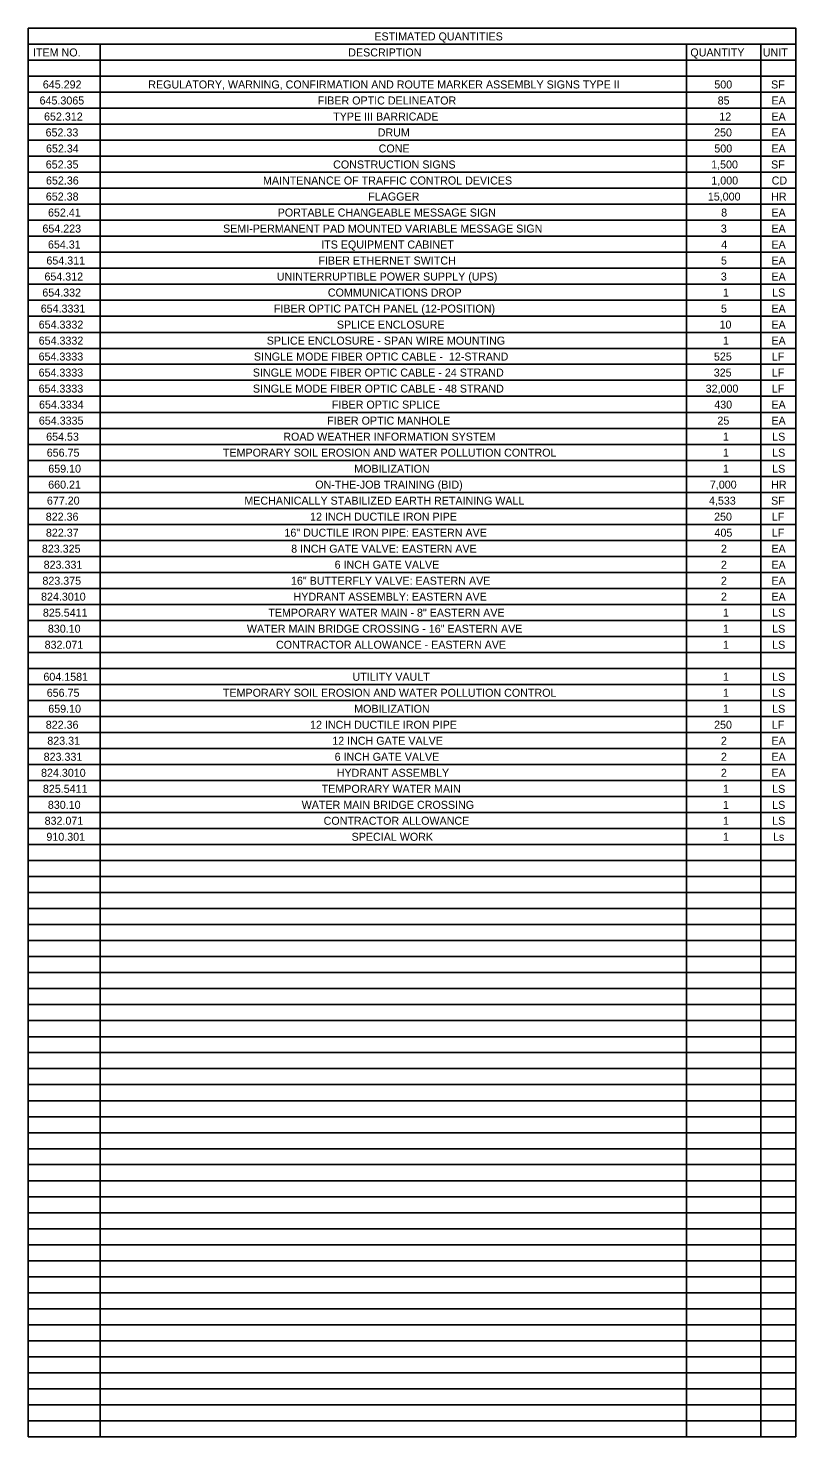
# Model space of a CAD drawing. Extents: x -18.7 to 5.6, y -2.7 to 4.
# Drawn here: x -5.186 to -4.242, y -0.822 to 0.91 of the extents above; entities that cross this region are included whole.
import ezdxf

# ---------------------------------------------------------------- set-up
doc = ezdxf.new("R2010")
doc.units = 0
doc.layers.add('ANNOTATION', color=7, linetype='Continuous')
doc.layers.add('BORDER', color=7, linetype='Continuous')

msp = doc.modelspace()

# ---------------------------------------------------------------- linework, layer by layer
at = {"layer": 'BORDER'}
for p, q in [((-5.186, 0.8907), (-4.2418, 0.8907)), ((-5.0975, 0.8907), (-5.0975, -0.822)), ((-4.3761, 0.8907), (-4.3761, -0.822)), ((-4.2848, 0.8907), (-4.2848, -0.822)), ((-5.186, 0.871), (-4.2418, 0.871)), ((-5.186, 0.8513), (-4.2418, 0.8513)), ((-5.186, 0.8316), (-4.2418, 0.8316)), ((-5.186, 0.8119), (-4.2418, 0.8119)), ((-5.186, 0.7922), (-4.2418, 0.7922)), ((-5.186, 0.7726), (-4.2418, 0.7726)), ((-5.186, 0.7529), (-4.2418, 0.7529)), ((-5.186, 0.7332), (-4.2418, 0.7332)), ((-5.186, 0.7135), (-4.2418, 0.7135)), ((-5.186, 0.6938), (-4.2418, 0.6938)), ((-5.186, 0.6741), (-4.2418, 0.6741)), ((-5.186, 0.6544), (-4.2418, 0.6544)), ((-5.186, 0.6348), (-4.2418, 0.6348)), ((-5.186, 0.6151), (-4.2418, 0.6151)), ((-5.186, 0.5954), (-4.2418, 0.5954)), ((-5.186, 0.5757), (-4.2418, 0.5757)), ((-5.186, 0.556), (-4.2418, 0.556)), ((-5.186, 0.5363), (-4.2418, 0.5363)), ((-5.186, 0.5166), (-4.2418, 0.5166)), ((-5.186, 0.497), (-4.2418, 0.497)), ((-5.186, 0.4773), (-4.2418, 0.4773)), ((-5.186, 0.4576), (-4.2418, 0.4576)), ((-5.186, 0.4379), (-4.2418, 0.4379)), ((-5.186, 0.4182), (-4.2418, 0.4182)), ((-5.186, 0.3985), (-4.2418, 0.3985)), ((-5.186, 0.3788), (-4.2418, 0.3788)), ((-5.186, 0.3592), (-4.2418, 0.3592)), ((-5.186, 0.3395), (-4.2418, 0.3395)), ((-5.186, 0.3198), (-4.2418, 0.3198)), ((-5.186, 0.3001), (-4.2418, 0.3001)), ((-5.186, 0.2804), (-4.2418, 0.2804)), ((-5.186, 0.2607), (-4.2418, 0.2607)), ((-5.186, 0.241), (-4.2418, 0.241)), ((-5.186, 0.2214), (-4.2418, 0.2214)), ((-5.186, 0.2017), (-4.2418, 0.2017)), ((-5.186, 0.182), (-4.2418, 0.182)), ((-5.186, 0.1623), (-4.2418, 0.1623)), ((-5.186, 0.1426), (-4.2418, 0.1426)), ((-5.186, 0.1229), (-4.2418, 0.1229)), ((-5.186, 0.1032), (-4.2418, 0.1032)), ((-5.186, 0.0835), (-4.2418, 0.0835)), ((-5.186, 0.0639), (-4.2418, 0.0639)), ((-5.186, 0.0442), (-4.2418, 0.0442)), ((-5.186, 0.0245), (-4.2418, 0.0245)), ((-5.186, 0.0048), (-4.2418, 0.0048)), ((-5.186, -0.0149), (-4.2418, -0.0149)), ((-5.186, -0.0346), (-4.2418, -0.0346)), ((-5.186, -0.0543), (-4.2418, -0.0543)), ((-5.186, -0.0739), (-4.2418, -0.0739)), ((-5.186, -0.0936), (-4.2418, -0.0936)), ((-5.186, -0.1133), (-4.2418, -0.1133)), ((-5.186, -0.133), (-4.2418, -0.133)), ((-5.186, -0.1527), (-4.2418, -0.1527)), ((-5.186, -0.1724), (-4.2418, -0.1724)), ((-5.186, -0.1921), (-4.2418, -0.1921)), ((-5.186, -0.2117), (-4.2418, -0.2117)), ((-5.186, -0.2314), (-4.2418, -0.2314)), ((-5.186, -0.2511), (-4.2418, -0.2511)), ((-5.186, -0.2708), (-4.2418, -0.2708)), ((-5.186, -0.2905), (-4.2418, -0.2905)), ((-5.186, -0.3102), (-4.2418, -0.3102)), ((-5.186, -0.3299), (-4.2418, -0.3299)), ((-5.186, -0.3495), (-4.2418, -0.3495)), ((-5.186, -0.3692), (-4.2418, -0.3692)), ((-5.186, -0.3889), (-4.2418, -0.3889)), ((-5.186, -0.4086), (-4.2418, -0.4086)), ((-5.186, -0.4283), (-4.2418, -0.4283)), ((-5.186, -0.448), (-4.2418, -0.448)), ((-5.186, -0.4677), (-4.2418, -0.4677)), ((-5.186, -0.4873), (-4.2418, -0.4873)), ((-5.186, -0.507), (-4.2418, -0.507)), ((-5.186, -0.5267), (-4.2418, -0.5267)), ((-5.186, -0.5464), (-4.2418, -0.5464)), ((-5.186, -0.5661), (-4.2418, -0.5661)), ((-5.186, -0.5858), (-4.2418, -0.5858)), ((-5.186, -0.6055), (-4.2418, -0.6055)), ((-5.186, -0.6251), (-4.2418, -0.6251)), ((-5.186, -0.6448), (-4.2418, -0.6448)), ((-5.186, -0.6645), (-4.2418, -0.6645)), ((-5.186, -0.6842), (-4.2418, -0.6842)), ((-5.186, -0.7039), (-4.2418, -0.7039)), ((-5.186, -0.7236), (-4.2418, -0.7236)), ((-5.186, -0.7433), (-4.2418, -0.7433)), ((-5.186, -0.7629), (-4.2418, -0.7629)), ((-5.186, -0.7826), (-4.2418, -0.7826)), ((-5.186, -0.8023), (-4.2418, -0.8023)), ((-5.186, -0.822), (-4.2418, -0.822))]:
    msp.add_line(p, q, dxfattribs=at)
msp.add_lwpolyline([(-5.186, 0.9104), (-4.2418, 0.9104), (-4.2418, -0.822), (-5.186, -0.822)], close=True, dxfattribs=at)

# ---------------------------------------------------------------- texts
at = {"layer": 'ANNOTATION'}
for s, height, p in [('645.292', 0.00984, (-5.168, 0.8362)), ('REGULATORY, WARNING, CONFIRMATION AND ROUTE MARKER ASSEMBLY SIGNS TYPE II', 0.009843, (-5.0383, 0.8362)), ('500', 0.00984, (-4.342, 0.8362)), ('SF', 0.00984, (-4.2722, 0.8362)), ('645.3065', 0.00984, (-5.172, 0.8165)), ('FIBER OPTIC DELINEATOR', 0.009843, (-4.8299, 0.8165)), ('85', 0.00984, (-4.3379, 0.8165)), ('EA', 0.00984, (-4.2718, 0.8165)), ('652.312', 0.00984, (-5.1665, 0.7968)), ('TYPE III BARRICADE', 0.009843, (-4.8108, 0.7968)), ('12', 0.00984, (-4.3359, 0.7968)), ('EA', 0.00984, (-4.2718, 0.7968)), ('652.33', 0.00984, (-5.1646, 0.7772)), ('DRUM', 0.00984, (-4.7561, 0.7772)), ('250', 0.00984, (-4.3423, 0.7772)), ('EA', 0.00984, (-4.2718, 0.7772)), ('652.34', 0.00984, (-5.1641, 0.7575)), ('CONE', 0.00984, (-4.7549, 0.7575)), ('500', 0.00984, (-4.342, 0.7575)), ('EA', 0.00984, (-4.2718, 0.7575)), ('652.35', 0.00984, (-5.1644, 0.7378)), ('CONSTRUCTION SIGNS', 0.009843, (-4.8109, 0.7378)), ('1,500', 0.00984, (-4.3459, 0.7378)), ('SF', 0.00984, (-4.2722, 0.7378)), ('652.36', 0.00984, (-5.1641, 0.7181)), ('MAINTENANCE OF TRAFFIC CONTROL DEVICES', 0.009843, (-4.8972, 0.7181)), ('1,000', 0.00984, (-4.3457, 0.7181)), ('CD', 0.00984, (-4.2715, 0.7181)), ('652.38', 0.00984, (-5.1643, 0.6984)), ('FLAGGER', 0.00984, (-4.7677, 0.6984)), ('15,000', 0.00984, (-4.35, 0.6984)), ('HR', 0.00984, (-4.2722, 0.6984)), ('652.41', 0.00984, (-5.1616, 0.6787)), ('PORTABLE CHANGEABLE MESSAGE SIGN', 0.009843, (-4.8791, 0.6787)), ('8', 0.00984, (-4.3336, 0.6787)), ('EA', 0.00984, (-4.2718, 0.6787)), ('654.223', 0.00984, (-5.1685, 0.659)), ('SEMI-PERMANENT PAD MOUNTED VARIABLE MESSAGE SIGN', 0.009843, (-4.9463, 0.659)), ('3', 0.00984, (-4.334, 0.659)), ('EA', 0.00984, (-4.2718, 0.659)), ('654.31', 0.00984, (-5.1617, 0.6394)), ('ITS EQUIPMENT CABINET  ', 0.009843, (-4.8256, 0.6394)), ('4', 0.00984, (-4.3335, 0.6394)), ('EA', 0.00984, (-4.2718, 0.6394)), ('654.311', 0.00984, (-5.1636, 0.6197)), ('FIBER ETHERNET SWITCH ', 0.009843, (-4.829, 0.6197)), ('5', 0.00984, (-4.3338, 0.6197)), ('EA', 0.00984, (-4.2718, 0.6197)), ('654.312', 0.00984, (-5.166, 0.6)), ('UNINTERRUPTIBLE POWER SUPPLY (UPS)', 0.009843, (-4.8802, 0.6)), ('3', 0.00984, (-4.334, 0.6)), ('EA', 0.00984, (-4.2718, 0.6)), ('654.332', 0.00984, (-5.1686, 0.5803)), ('COMMUNICATIONS DROP', 0.009843, (-4.8174, 0.5803)), ('1', 0.00984, (-4.3315, 0.5803)), ('LS', 0.00984, (-4.2708, 0.5803)), ('654.3331', 0.00984, (-5.1706, 0.5606)), ('FIBER OPTIC PATCH PANEL (12-POSITION)', 0.009843, (-4.8838, 0.5606)), ('5', 0.00984, (-4.3338, 0.5606)), ('EA', 0.00984, (-4.2718, 0.5606)), ('654.3332', 0.00984, (-5.1731, 0.5409)), ('SPLICE ENCLOSURE', 0.009843, (-4.8063, 0.5409)), ('10', 0.00984, (-4.3356, 0.5409)), ('EA', 0.00984, (-4.2718, 0.5409)), ('654.3332', 0.00984, (-5.1731, 0.5212)), ('SPLICE ENCLOSURE - SPAN WIRE MOUNTING', 0.009843, (-4.8926, 0.5212)), ('1', 0.00984, (-4.3315, 0.5212)), ('EA', 0.00984, (-4.2718, 0.5212)), ('654.3333', 0.00984, (-5.1732, 0.5016)), ('SINGLE MODE FIBER OPTIC CABLE -  12-STRAND', 0.009843, (-4.9084, 0.5016)), ('525', 0.00984, (-4.3425, 0.5016)), ('LF', 0.00984, (-4.2712, 0.5016)), ('654.3333', 0.00984, (-5.1732, 0.4819)), ('SINGLE MODE FIBER OPTIC CABLE - 24 STRAND', 0.009843, (-4.9097, 0.4819)), ('325', 0.00984, (-4.3427, 0.4819)), ('LF', 0.00984, (-4.2712, 0.4819)), ('654.3333', 0.00984, (-5.1732, 0.4622)), ('SINGLE MODE FIBER OPTIC CABLE - 48 STRAND', 0.009843, (-4.9096, 0.4622)), ('32,000', 0.00984, (-4.3527, 0.4622)), ('LF', 0.00984, (-4.2712, 0.4622)), ('654.3334', 0.00984, (-5.1727, 0.4425)), ('FIBER OPTIC SPLICE ', 0.009843, (-4.8124, 0.4425)), ('430', 0.00984, (-4.3421, 0.4425)), ('EA', 0.00984, (-4.2718, 0.4425)), ('654.3335', 0.00984, (-5.1729, 0.4228)), ('FIBER OPTIC MANHOLE ', 0.009843, (-4.8183, 0.4228)), ('25', 0.00984, (-4.3382, 0.4228)), ('EA', 0.00984, (-4.2718, 0.4228)), ('654.53', 0.00984, (-5.1639, 0.4031)), ('ROAD WEATHER INFORMATION SYSTEM', 0.009843, (-4.8722, 0.4031)), ('1', 0.00984, (-4.3315, 0.4031)), ('LS', 0.00984, (-4.2708, 0.4031)), ('656.75', 0.00984, (-5.1632, 0.3834)), ('TEMPORARY SOIL EROSION AND WATER POLLUTION CONTROL', 0.009843, (-4.9465, 0.3834)), ('1', 0.00984, (-4.3315, 0.3834)), ('LS', 0.00984, (-4.2708, 0.3834)), ('659.10', 0.00984, (-5.1613, 0.3637)), ('MOBILIZATION', 0.009843, (-4.785, 0.3637)), ('1', 0.00984, (-4.3315, 0.3637)), ('LS', 0.00984, (-4.2708, 0.3637)), ('660.21', 0.00984, (-5.1614, 0.3441)), ('ON-THE-JOB TRAINING (BID)', 0.009843, (-4.8329, 0.3441)), ('7,000', 0.00984, (-4.3475, 0.3441)), ('HR', 0.00984, (-4.2722, 0.3441)), ('677.20', 0.00984, (-5.163, 0.3244)), ('MECHANICALLY STABILIZED EARTH RETAINING WALL', 0.009843, (-4.9201, 0.3244)), ('4,533', 0.00984, (-4.3486, 0.3244)), ('SF', 0.00984, (-4.2722, 0.3244)), ('822.36', 0.00984, (-5.1644, 0.3047)), ('12 INCH DUCTILE IRON PIPE', 0.009843, (-4.8393, 0.3047)), ('250', 0.00984, (-4.3423, 0.3047)), ('LF', 0.00984, (-4.2712, 0.3047)), ('822.37', 0.00984, (-5.1642, 0.285)), ('16" DUCTILE IRON PIPE: EASTERN AVE', 0.009843, (-4.8708, 0.285)), ('405', 0.00984, (-4.3418, 0.285)), ('LF', 0.00984, (-4.2712, 0.285)), ('823.325', 0.00984, (-5.1692, 0.2653)), ('8 INCH GATE VALVE: EASTERN AVE', 0.009843, (-4.8625, 0.2653)), ('2', 0.00984, (-4.3339, 0.2653)), ('EA', 0.00984, (-4.2718, 0.2653)), ('823.331', 0.00984, (-5.167, 0.2456)), ('6 INCH GATE VALVE', 0.009843, (-4.8091, 0.2456)), ('2', 0.00984, (-4.3339, 0.2456)), ('EA', 0.00984, (-4.2718, 0.2456)), ('823.375', 0.00984, (-5.1685, 0.2259)), ('16" BUTTERFLY VALVE: EASTERN AVE', 0.009843, (-4.8628, 0.2259)), ('2', 0.00984, (-4.3339, 0.2259)), ('EA', 0.00984, (-4.2718, 0.2259)), ('824.3010', 0.00984, (-5.1702, 0.2063)), ('HYDRANT ASSEMBLY: EASTERN AVE', 0.009843, (-4.8596, 0.2063)), ('2', 0.00984, (-4.3339, 0.2063)), ('EA', 0.00984, (-4.2718, 0.2063)), ('825.5411', 0.00984, (-5.1679, 0.1866)), ('TEMPORARY WATER MAIN - 8" EASTERN AVE', 0.009843, (-4.8906, 0.1866)), ('1', 0.00984, (-4.3315, 0.1866)), ('LS', 0.00984, (-4.2708, 0.1866)), ('830.10', 0.00984, (-5.1618, 0.1669)), ('WATER MAIN BRIDGE CROSSING - 16" EASTERN AVE', 0.009843, (-4.917, 0.1669)), ('1', 0.00984, (-4.3315, 0.1669)), ('LS', 0.00984, (-4.2708, 0.1669)), ('832.071', 0.00984, (-5.1658, 0.1472)), ('CONTRACTOR ALLOWANCE - EASTERN AVE', 0.009843, (-4.8812, 0.1472)), ('1', 0.00984, (-4.3315, 0.1472)), ('LS', 0.00984, (-4.2708, 0.1472)), ('604.1581', 0.00984, (-5.1673, 0.1078)), ('UTILITY VAULT', 0.009843, (-4.7871, 0.1078)), ('1', 0.00984, (-4.3315, 0.1078)), ('LS', 0.00984, (-4.2708, 0.1078)), ('656.75', 0.00984, (-5.1632, 0.0881)), ('TEMPORARY SOIL EROSION AND WATER POLLUTION CONTROL', 0.009843, (-4.9465, 0.0881)), ('1', 0.00984, (-4.3315, 0.0881)), ('LS', 0.00984, (-4.2708, 0.0881)), ('659.10', 0.00984, (-5.1613, 0.0685)), ('MOBILIZATION', 0.009843, (-4.785, 0.0685)), ('1', 0.00984, (-4.3315, 0.0685)), ('LS', 0.00984, (-4.2708, 0.0685)), ('822.36', 0.00984, (-5.1644, 0.0488)), ('12 INCH DUCTILE IRON PIPE', 0.009843, (-4.8393, 0.0488)), ('250', 0.00984, (-4.3423, 0.0488)), ('LF', 0.00984, (-4.2712, 0.0488)), ('823.31', 0.00984, (-5.1625, 0.0291)), ('12 INCH GATE VALVE', 0.009843, (-4.812, 0.0291)), ('2', 0.00984, (-4.3339, 0.0291)), ('EA', 0.00984, (-4.2718, 0.0291)), ('823.331', 0.00984, (-5.167, 0.0094)), ('6 INCH GATE VALVE', 0.009843, (-4.8091, 0.0094)), ('2', 0.00984, (-4.3339, 0.0094)), ('EA', 0.00984, (-4.2718, 0.0094)), ('824.3010', 0.00984, (-5.1702, -0.0103)), ('HYDRANT ASSEMBLY', 0.009843, (-4.8065, -0.0103)), ('2', 0.00984, (-4.3339, -0.0103)), ('EA', 0.00984, (-4.2718, -0.0103)), ('825.5411', 0.00984, (-5.1679, -0.03)), ('TEMPORARY WATER MAIN', 0.009843, (-4.825, -0.03)), ('1', 0.00984, (-4.3315, -0.03)), ('LS', 0.00984, (-4.2708, -0.03)), ('830.10', 0.00984, (-5.1618, -0.0497)), ('WATER MAIN BRIDGE CROSSING', 0.009843, (-4.8496, -0.0497)), ('1', 0.00984, (-4.3315, -0.0497)), ('LS', 0.00984, (-4.2708, -0.0497)), ('832.071', 0.00984, (-5.1658, -0.0693)), ('CONTRACTOR ALLOWANCE', 0.009843, (-4.8226, -0.0693)), ('1', 0.00984, (-4.3315, -0.0693)), ('LS', 0.00984, (-4.2708, -0.0693)), ('910.301', 0.00984, (-5.1636, -0.089)), ('SPECIAL WORK', 0.009843, (-4.7882, -0.089)), ('1', 0.00984, (-4.3315, -0.089)), ('Ls', 0.00984, (-4.2699, -0.089))]:
    msp.add_text(s, height=height, dxfattribs=at).set_placement(p)
at = {"layer": 'BORDER'}
for s, height, p in [('ESTIMATED QUANTITIES', 0.009843, (-4.7602, 0.8953)), ('ITEM NO.', 0.00984, (-5.1801, 0.8756)), ('DESCRIPTION', 0.009843, (-4.7923, 0.8756)), ('QUANTITY', 0.00984, (-4.3715, 0.8756)), ('UNIT', 0.00984, (-4.2824, 0.8756))]:
    msp.add_text(s, height=height, dxfattribs=at).set_placement(p)

doc.saveas('drawing.dxf')
